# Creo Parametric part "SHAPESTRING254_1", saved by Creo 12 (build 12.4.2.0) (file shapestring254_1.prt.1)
Units: Custom; MM, KILOGRAM, SECS

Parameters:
  PTC_WM_ITERATION = "0"
  PTC_WM_VERSION = "-.0"
  PTC_WM_LIFECYCLE_STATE = "In Work"
  PTC_WM_LIFECYCLE = "MO_CADDocument"
  PTC_WM_CREATED_BY = "Maximilian Roepper (Z0017RMS: MO)"
  PTC_WM_CREATED_ON = "18-Sep-26 11:36:42 AM"
  PTC_WM_MODIFIED_BY = "Maximilian Roepper (Z0017RMS: MO)"
  PTC_WM_MODIFIED_ON = "18-Sep-26 11:36:46 AM"
  PDMLINKNUMBER = "PDM000071455002"
  PTC_WM_NAME = "shapestring254_1.prt"
  PTC_WM_NUMBER = "PDM000071455002"

Other parameters: WEIGHT, WEIGHT_FACTOR, WEIGHT_ADD, _MASS_TEMP, _DIFF_TEMP, MC_ERRORS, SUPPLIER

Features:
  1. coordinate system
  2. datum plane "PRT_YZ"
  3. datum plane "PRT_XY"
  4. datum plane "PRT_XZ"
  5. coordinate system
  6. datum axis
  7. datum axis
  8. datum axis
  9. coordinate system
  10. imported feature
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
Other named items: PRT, SIEMENS_MO, DRW_VIEW_ORG, PRT_X, PRT_Y, PRT_Z, CS0, ROUGH_GROB

Layers: 00_STD_CSYS-KSYS, 01_STD_PLANES-EBENEN, 02_STD_AXES-ACHSEN, 03_STD_CSYS-KSYS, 24_IMPORT_FEAT-IMPORT_KE, WHITE

Surfaces: 1 plane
